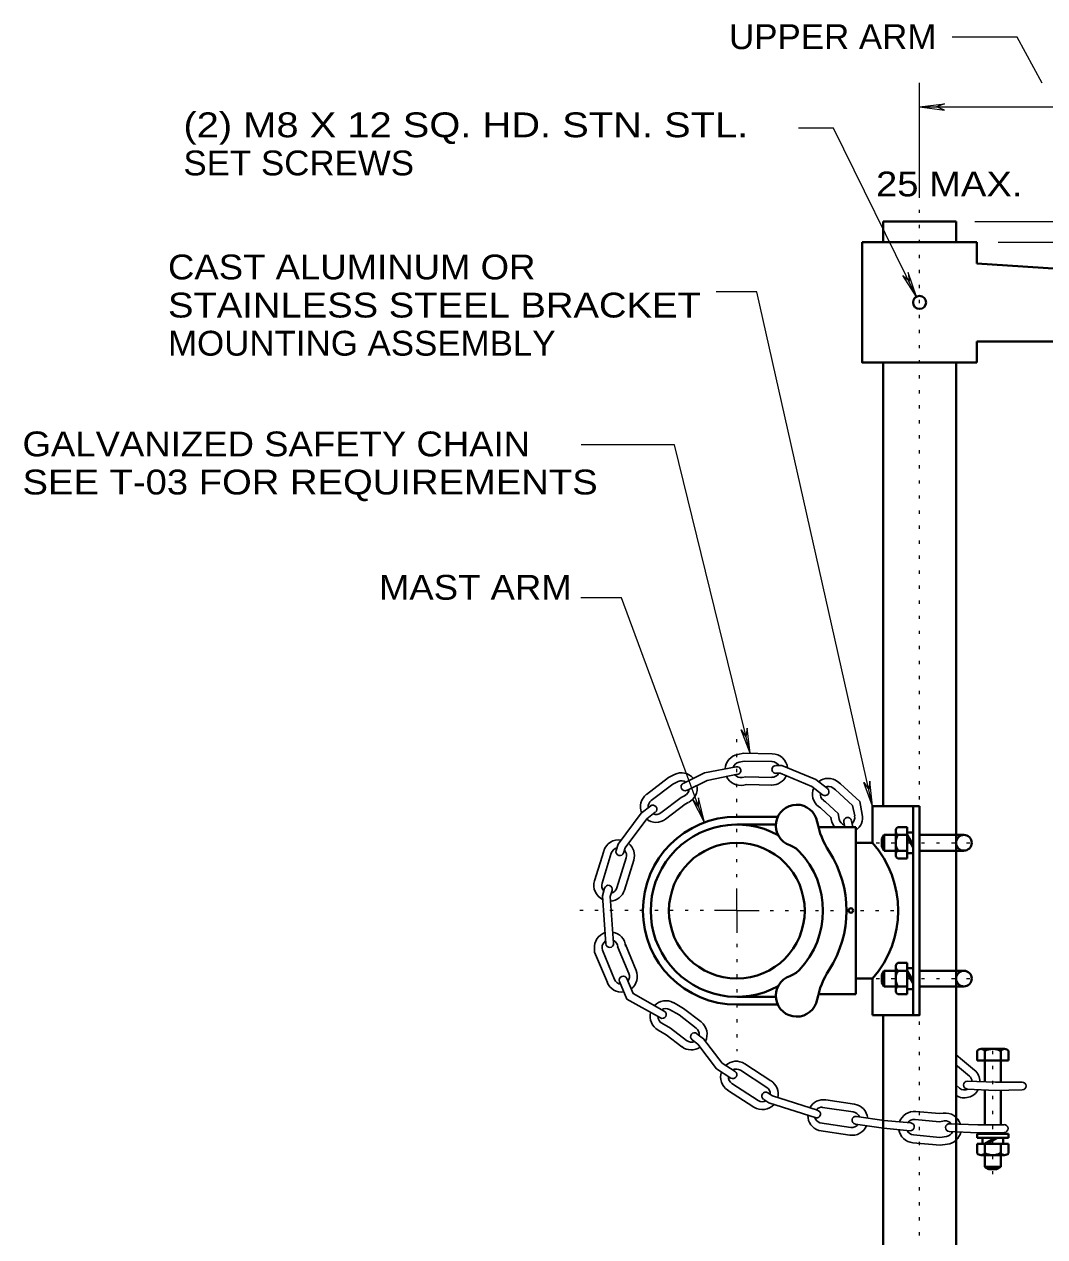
# Model space of a CAD drawing. Extents: x 312583 to 312854, y 144419 to 144597.
# Drawn here: x 312713.71 to 312744.93, y 144479.26 to 144516.36 of the extents above; entities that cross this region are included whole.
import ezdxf

# ---------------------------------------------------------------- set-up
doc = ezdxf.new("R2010")
doc.units = 0
doc.header["$LTSCALE"] = 0.3
doc.linetypes.add('DOTTED', pattern=[1.5, 0.3, -1.2])
doc.layers.add('1', color=7, linetype='Continuous', lineweight=40)
doc.layers.add('2', color=7, linetype='Continuous', lineweight=40)

msp = doc.modelspace()

# ---------------------------------------------------------------- linework, layer by layer
at = {"layer": '1', "linetype": 'DOTTED', "lineweight": 13}
for p, q in [((312741.0994, 144459.9829), (312741.0994, 144511.0659)), ((312739.7731, 144491.3165), (312742.9854, 144491.3165)), ((312739.7731, 144487.1612), (312742.8858, 144487.1612)), ((312743.3381, 144481.1735), (312743.3381, 144485.1832))]:
    msp.add_line(p, q, dxfattribs=at)
at = {"layer": '1'}
for p, q in [((312739.9801, 144509.6859), (312739.9801, 144510.3222)), ((312739.9801, 144510.3222), (312742.2188, 144510.3222)), ((312742.2188, 144509.6859), (312742.2188, 144510.3222)), ((312739.3438, 144509.6859), (312742.8551, 144509.6859)), ((312742.8551, 144509.6859), (312742.8551, 144509.0419)), ((312742.8551, 144509.0419), (312751.8864, 144508.4209)), ((312742.8551, 144506.6499), (312749.7244, 144506.6499)), ((312742.8551, 144506.6499), (312742.8551, 144506.0059)), ((312739.9801, 144492.4359), (312739.9801, 144506.0059)), ((312742.2188, 144466.0779), (312742.2188, 144506.0059)), ((312735.5104, 144492.1139), (312736.7601, 144492.1139)), ((312735.5104, 144491.8762), (312736.6988, 144491.8762)), ((312739.1521, 144491.7919), (312738.0021, 144491.7919)), ((312739.1521, 144491.7919), (312739.1521, 144486.6859)), ((312739.9418, 144491.4315), (312740.0108, 144491.5542)), ((312740.0108, 144491.5542), (312740.0108, 144491.0712)), ((312740.0108, 144491.5542), (312740.3711, 144491.5542)), ((312740.3711, 144491.6769), (312740.3711, 144490.9485)), ((312740.4324, 144491.7919), (312740.7238, 144491.7919)), ((312740.4324, 144491.5542), (312740.7238, 144491.5542)), ((312740.7238, 144491.7919), (312740.7238, 144490.8335)), ((312740.7238, 144491.6309), (312740.9078, 144491.6309)), ((312740.7238, 144491.5542), (312740.9078, 144491.2399)), ((312740.7238, 144491.4929), (312740.9078, 144491.1709)), ((312740.9078, 144491.6309), (312740.9078, 144490.9945)), ((312741.0994, 144491.5542), (312742.4564, 144491.5542)), ((312739.6581, 144491.3165), (312739.1521, 144491.3165)), ((312739.9418, 144491.4315), (312739.9418, 144491.2015)), ((312739.9418, 144491.2015), (312740.0108, 144491.0712)), ((312740.0108, 144491.0712), (312740.3711, 144491.0712)), ((312740.4324, 144491.0712), (312740.7238, 144491.0712)), ((312740.4324, 144490.8335), (312740.7238, 144490.8335)), ((312740.7238, 144490.9945), (312740.9078, 144490.9945)), ((312741.0994, 144491.0712), (312742.4564, 144491.0712)), ((312739.9418, 144487.2762), (312740.0108, 144487.3989)), ((312740.0108, 144487.3989), (312740.0108, 144486.9235)), ((312740.0108, 144487.3989), (312740.3711, 144487.3989)), ((312740.3711, 144487.5215), (312740.3711, 144486.8009)), ((312740.4324, 144487.6442), (312740.7238, 144487.6442)), ((312740.4324, 144487.3989), (312740.7238, 144487.3989)), ((312740.7238, 144487.6442), (312740.7238, 144486.6859)), ((312740.7238, 144487.4832), (312740.9078, 144487.4832)), ((312740.7238, 144487.3989), (312740.9078, 144487.0845)), ((312740.9078, 144487.4832), (312740.9078, 144486.8392)), ((312741.0994, 144487.3989), (312742.4564, 144487.3989)), ((312739.6581, 144487.1612), (312739.1521, 144487.1612)), ((312739.6581, 144486.0419), (312739.6581, 144487.1612)), ((312739.9418, 144487.2762), (312739.9418, 144487.0462)), ((312739.9418, 144487.0462), (312740.0108, 144486.9235)), ((312740.7238, 144487.3375), (312740.9078, 144487.0232)), ((312739.1521, 144486.6859), (312738.0021, 144486.6859)), ((312740.0108, 144486.9235), (312740.3711, 144486.9235)), ((312740.4324, 144486.9235), (312740.7238, 144486.9235)), ((312740.4324, 144486.6859), (312740.7238, 144486.6859)), ((312740.7238, 144486.8392), (312740.9078, 144486.8392)), ((312741.0994, 144486.9235), (312742.4564, 144486.9235)), ((312735.5104, 144486.6015), (312736.6988, 144486.6015)), ((312735.5104, 144486.3639), (312736.7601, 144486.3639)), ((312739.9801, 144476.1442), (312739.9801, 144486.0419)), ((312742.8628, 144484.9532), (312742.8628, 144484.6542)), ((312742.9778, 144485.0069), (312743.7061, 144485.0069)), ((312743.1004, 144483.9949), (312743.1004, 144484.9532)), ((312743.5834, 144483.9872), (312743.5834, 144484.9532)), ((312743.8211, 144484.9532), (312743.8211, 144484.6542)), ((312742.8628, 144484.6542), (312743.8211, 144484.6542)), ((312743.1004, 144482.6839), (312743.1004, 144483.7572)), ((312743.5834, 144482.6915), (312743.5834, 144483.7495)), ((312742.8628, 144482.4079), (312743.8211, 144482.4079)), ((312742.8628, 144482.2929), (312742.8628, 144482.4079)), ((312742.8628, 144482.2929), (312743.8211, 144482.2929)), ((312743.0238, 144482.1089), (312743.0238, 144482.2929)), ((312743.1004, 144482.4079), (312743.1004, 144482.4462)), ((312743.1004, 144482.1089), (312743.4148, 144482.2929)), ((312743.1618, 144482.1089), (312743.4838, 144482.2929)), ((312743.5834, 144482.4079), (312743.5834, 144482.4539)), ((312743.6601, 144482.1089), (312743.6601, 144482.2929)), ((312743.8211, 144482.2929), (312743.8211, 144482.4079)), ((312742.8628, 144482.1089), (312743.8211, 144482.1089)), ((312742.8628, 144481.8175), (312742.8628, 144482.1089)), ((312743.1004, 144481.8175), (312743.1004, 144482.1089)), ((312743.5834, 144481.8175), (312743.5834, 144482.1089)), ((312743.8211, 144481.8175), (312743.8211, 144482.1089)), ((312742.9778, 144481.7562), (312743.7061, 144481.7562)), ((312743.1004, 144481.4035), (312743.1004, 144481.7562)), ((312743.5834, 144481.4035), (312743.5834, 144481.7562)), ((312743.1004, 144481.4035), (312743.5834, 144481.4035)), ((312743.2231, 144481.3269), (312743.1004, 144481.4035)), ((312743.2231, 144481.3269), (312743.4531, 144481.3269)), ((312743.4531, 144481.3269), (312743.5834, 144481.4035))]:
    msp.add_line(p, q, dxfattribs=at)
at = {"layer": '1', "lineweight": 25}
for p, q in [((312742.4104, 144484.6695), (312742.2188, 144484.8305)), ((312742.2571, 144484.4855), (312742.2188, 144484.5162)), ((312742.2571, 144484.4855), (312742.6251, 144484.1789)), ((312742.4104, 144484.6695), (312742.7784, 144484.3552)), ((312742.3184, 144483.8109), (312742.2188, 144483.8952))]:
    msp.add_line(p, q, dxfattribs=at)
at = {"layer": '1'}
for points in [[(312739.3438, 144509.6859), (312739.3438, 144506.0059), (312742.8551, 144506.0059)], [(312741.0994, 144492.4359), (312741.0994, 144486.0419), (312739.6581, 144486.0419)], [(312741.0994, 144492.4359), (312739.6581, 144492.4359), (312739.6581, 144491.3165)], [(312741.0994, 144492.4359), (312740.9078, 144492.4359), (312740.9078, 144486.0419)]]:
    msp.add_lwpolyline(points, dxfattribs=at)
for centre, radius in [((312741.0982, 144507.8459), 0.1996), ((312742.4558, 144491.3146), 0.2396), ((312735.5079, 144489.2382), 2.0764), ((312738.9968, 144489.2446), 0.0679), ((312742.4558, 144487.1618), 0.2396)]:
    msp.add_circle(centre, radius, dxfattribs=at)
for centre, radius, start, end in [((312735.5079, 144489.2382), 2.875, 90, 270), ((312735.5079, 144489.2382), 2.6354, 61.35961, 298.6449), ((312740.4794, 144492.4334), 2.5556, 190.67393, 212.72852), ((312740.5225, 144491.674), 0.1515, 127.72221, 232.27779), ((312740.8887, 144491.3146), 0.5176, 152.42977, 207.57023), ((312735.5079, 144489.2382), 2.6354, 316.47333, 43.52667), ((312735.5079, 144489.2382), 3.3542, 327.27148, 32.72852), ((312740.5225, 144490.9552), 0.1515, 127.72221, 232.27779), ((312740.4794, 144486.0431), 2.5556, 147.27148, 169.32607), ((312740.5225, 144487.5212), 0.1515, 127.72221, 232.27779), ((312740.8887, 144487.1618), 0.5176, 152.42977, 207.57023), ((312740.5225, 144486.8025), 0.1515, 127.72221, 232.27779), ((312742.9806, 144484.858), 0.1515, 37.72221, 142.27779), ((312743.34, 144484.4918), 0.5176, 62.42977, 117.57023), ((312743.6994, 144484.858), 0.1515, 37.72221, 142.27779), ((312742.9806, 144481.9115), 0.1515, 217.72221, 322.27779), ((312743.34, 144482.2777), 0.5176, 242.42977, 297.57023), ((312743.6994, 144481.9115), 0.1515, 217.72221, 322.27779)]:
    msp.add_arc(centre, radius, start, end, dxfattribs=at)
at = {"layer": '2', "lineweight": 13}
for p, q in [((312744.0818, 144515.9649), (312742.0961, 144515.9649)), ((312744.8484, 144514.5542), (312744.0818, 144515.9649)), ((312741.0994, 144511.0659), (312741.0994, 144514.5619)), ((312741.0994, 144513.8259), (312741.8661, 144513.9179)), ((312741.0994, 144513.8259), (312753.2204, 144513.8259)), ((312741.0994, 144513.8259), (312741.8661, 144513.7262)), ((312741.8661, 144513.9179), (312741.6208, 144513.8259)), ((312741.8661, 144513.7262), (312741.6208, 144513.8259)), ((312738.4621, 144513.1742), (312737.3964, 144513.1742)), ((312741.0074, 144508.0222), (312738.4621, 144513.1742)), ((312742.7861, 144510.3222), (312746.5044, 144510.3222)), ((312743.4991, 144509.6859), (312746.9874, 144509.6859)), ((312740.5858, 144508.6739), (312740.7774, 144508.4975)), ((312741.0074, 144508.0222), (312740.5858, 144508.6739)), ((312740.7544, 144508.7582), (312740.7774, 144508.4975)), ((312741.0074, 144508.0222), (312740.7544, 144508.7582)), ((312736.1238, 144508.1679), (312734.8741, 144508.1679)), ((312739.6581, 144492.4359), (312736.1238, 144508.1679)), ((312733.6014, 144503.4912), (312730.7494, 144503.4912)), ((312735.9168, 144494.0535), (312733.6014, 144503.4912)), ((312731.9838, 144498.8069), (312730.7341, 144498.8069)), ((312734.5138, 144491.9375), (312731.9838, 144498.8069)), ((312735.8248, 144494.8202), (312735.7864, 144494.5595)), ((312735.9168, 144494.0535), (312735.8248, 144494.8202)), ((312735.6408, 144494.7742), (312735.7864, 144494.5595)), ((312735.9168, 144494.0535), (312735.6408, 144494.7742)), ((312739.3974, 144493.1642), (312739.5431, 144492.9419)), ((312739.6581, 144492.4359), (312739.3974, 144493.1642)), ((312739.5814, 144493.2025), (312739.5431, 144492.9419)), ((312739.6581, 144492.4359), (312739.5814, 144493.2025)), ((312734.1611, 144492.6275), (312734.3298, 144492.4282)), ((312734.5138, 144491.9375), (312734.1611, 144492.6275)), ((312734.3374, 144492.6889), (312734.3298, 144492.4282)), ((312734.5138, 144491.9375), (312734.3374, 144492.6889)), ((312735.5104, 144489.2389), (312735.5104, 144489.9212)), ((312735.5104, 144489.2389), (312734.8281, 144489.2389)), ((312735.5104, 144489.2389), (312736.1928, 144489.2389)), ((312735.5104, 144489.2389), (312735.5104, 144488.5565))]:
    msp.add_line(p, q, dxfattribs=at)
at = {"layer": '2', "linetype": 'DOTTED', "lineweight": 13}
for p, q in [((312735.5104, 144490.2585), (312735.5104, 144494.4829)), ((312734.4831, 144489.2389), (312730.5501, 144489.2389)), ((312736.5301, 144489.2389), (312740.4401, 144489.2389)), ((312735.5104, 144488.2192), (312735.5104, 144484.9455))]:
    msp.add_line(p, q, dxfattribs=at)
at = {"layer": '2', "lineweight": 25}
for p, q in [((312738.7841, 144491.9452), (312738.8148, 144491.7919)), ((312739.0141, 144491.9912), (312739.0524, 144491.7919)), ((312731.1558, 144490.1512), (312731.4394, 144491.0635)), ((312731.3858, 144490.0822), (312731.6618, 144490.9945)), ((312731.8381, 144489.9365), (312732.1218, 144490.8565)), ((312732.0681, 144489.8675), (312732.3518, 144490.7875)), ((312736.5531, 144484.0332), (312735.7481, 144484.5545)), ((312736.4228, 144483.8339), (312735.6178, 144484.3552)), ((312736.0318, 144483.2282), (312735.2268, 144483.7495)), ((312736.1621, 144483.4275), (312735.3571, 144483.9489)), ((312739.1061, 144483.3202), (312738.2321, 144483.4505)), ((312739.0678, 144483.0825), (312738.1248, 144483.2205)), ((312738.9988, 144482.6072), (312738.0481, 144482.7452)), ((312738.9681, 144482.3695), (312738.0174, 144482.5152))]:
    msp.add_line(p, q, dxfattribs=at)
for points in [[(312735.5334, 144494.0152), (312735.7174, 144494.0535), (312736.5914, 144494.0382)], [(312735.5794, 144493.7852), (312735.7328, 144493.8159), (312736.5838, 144493.8005)], [(312732.7428, 144492.7962), (312733.4174, 144493.3175), (312733.6014, 144493.4019)], [(312733.8698, 144493.1335), (312734.5214, 144493.4555), (312735.4874, 144493.6395)], [(312733.9771, 144492.9189), (312734.5981, 144493.2255), (312735.5334, 144493.4095)], [(312735.6714, 144493.3175), (312735.7788, 144493.3329), (312736.5761, 144493.3175)], [(312736.6988, 144493.4402), (312736.8368, 144493.4402), (312737.8028, 144493.0415), (312738.1324, 144492.7809)], [(312736.7064, 144493.6779), (312736.8828, 144493.6779), (312737.9254, 144493.2485), (312738.2781, 144492.9725)], [(312732.8884, 144492.6122), (312733.5478, 144493.1105), (312733.7088, 144493.1872)], [(312735.7174, 144493.0799), (312735.8018, 144493.0952), (312736.5761, 144493.0799)], [(312738.4468, 144492.9955), (312738.5311, 144492.9342), (312739.0448, 144492.4589), (312739.1138, 144492.1369)], [(312738.5924, 144493.1872), (312738.6844, 144493.1182), (312739.2671, 144492.5815), (312739.3438, 144492.1829)], [(312733.1798, 144492.2289), (312733.8008, 144492.7042), (312733.9234, 144492.7579)], [(312738.1554, 144492.6122), (312738.2168, 144492.5662), (312738.6078, 144492.2135), (312738.6384, 144492.0372)], [(312731.8151, 144491.0789), (312731.8764, 144491.2705), (312732.5818, 144492.2212), (312732.8731, 144492.4435)], [(312732.0451, 144491.0022), (312732.0911, 144491.1632), (312732.7581, 144492.0525), (312733.0111, 144492.2519)], [(312733.3254, 144492.0372), (312733.9234, 144492.4972), (312734.0231, 144492.5432)], [(312738.0098, 144492.4205), (312738.0634, 144492.3822), (312738.3854, 144492.0909), (312738.4084, 144491.9912)], [(312731.5008, 144488.2269), (312731.3934, 144489.6912), (312731.4624, 144489.9289)], [(312731.7384, 144488.2422), (312731.6311, 144489.6682), (312731.6924, 144489.8599)], [(312732.2061, 144487.3145), (312731.8611, 144488.1425), (312731.8688, 144488.1349)], [(312732.4284, 144487.4065), (312732.0988, 144488.2039), (312732.1064, 144488.1502)], [(312731.5468, 144487.0462), (312731.1558, 144487.9739), (312731.1481, 144488.0735)], [(312731.7614, 144487.1305), (312731.3934, 144488.0352), (312731.3858, 144488.0965)], [(312733.1721, 144485.9575), (312732.1448, 144486.5325), (312731.9224, 144487.0692)], [(312733.2871, 144486.1645), (312732.3364, 144486.7012), (312732.1448, 144487.1612)], [(312734.4141, 144485.8349), (312733.8774, 144486.2489), (312733.5708, 144486.4252)], [(312734.2684, 144485.6432), (312733.7471, 144486.0495), (312733.4481, 144486.2105)], [(312733.8238, 144485.0759), (312733.3484, 144485.4439), (312733.1031, 144485.5819)], [(312733.9694, 144485.2675), (312733.4788, 144485.6432), (312733.2181, 144485.7965)], [(312735.3264, 144484.1175), (312734.8894, 144484.4012), (312734.3144, 144485.1525), (312734.1381, 144485.2905)], [(312735.4568, 144484.3169), (312735.0581, 144484.5775), (312734.4908, 144485.3212), (312734.2838, 144485.4745)], [(312744.2351, 144483.7572), (312743.4224, 144483.7419), (312742.5561, 144483.7802)], [(312744.2351, 144483.9949), (312743.4224, 144483.9872), (312742.5638, 144484.0179)], [(312737.9331, 144482.8985), (312736.4918, 144483.3585), (312736.3308, 144483.4659)], [(312737.9714, 144483.1362), (312736.5991, 144483.5732), (312736.4611, 144483.6652)], [(312740.8311, 144482.7452), (312740.0184, 144482.8219), (312739.1674, 144482.9445)], [(312741.8201, 144483.0442), (312741.7051, 144483.0289), (312740.9844, 144483.0902)], [(312740.8081, 144482.5075), (312739.9954, 144482.5842), (312739.1368, 144482.7069)], [(312741.8584, 144482.8065), (312741.7128, 144482.7835), (312740.9614, 144482.8525)], [(312743.6831, 144482.6915), (312742.8781, 144482.6839), (312742.0194, 144482.7222)], [(312741.9198, 144482.3312), (312741.7204, 144482.3005), (312740.9154, 144482.3772)], [(312743.6908, 144482.4539), (312742.8704, 144482.4462), (312742.0041, 144482.4845)], [(312741.9581, 144482.0935), (312741.7281, 144482.0629), (312740.8924, 144482.1395)]]:
    msp.add_lwpolyline(points, dxfattribs=at)
for centre, radius, start, end in [((312735.6264, 144493.5491), 0.4792, 101.14556, 176.62859), ((312735.6264, 144493.5491), 0.2396, 101.14556, 161.05731), ((312736.5818, 144493.5602), 0.2396, 29.0581, 88.96985), ((312736.5818, 144493.5602), 0.4792, 5.05092, 89.00409), ((312733.8147, 144492.9752), 0.4792, 40.56675, 116.04979), ((312735.6264, 144493.5491), 0.4792, 205.50476, 281.14556), ((312735.6264, 144493.5491), 0.2396, 220.88127, 281.14556), ((312735.5086, 144493.5259), 0.1195, 281.14556, 101.14556), ((312736.5818, 144493.5602), 0.4792, 268.93347, 335.48236), ((312736.5818, 144493.5602), 0.2396, 268.96985, 329.23414), ((312736.7019, 144493.558), 0.1195, 88.96985, 268.96985), ((312733.8147, 144492.9752), 0.2396, 56.13804, 116.04979), ((312733.9226, 144493.028), 0.1195, 116.04979, 296.04979), ((312733.8147, 144492.9752), 0.2396, 296.04979, 356.31408), ((312733.8147, 144492.9752), 0.4792, 296.04979, 11.69059), ((312738.3012, 144492.8044), 0.4792, 156.84249, 232.4833), ((312738.3012, 144492.8044), 0.4792, 52.4833, 127.96633), ((312738.2059, 144492.8776), 0.1195, 232.4833, 52.4833), ((312738.3012, 144492.8044), 0.2396, 52.4833, 112.39505), ((312733.0374, 144492.4195), 0.4792, 127.41484, 202.89787), ((312733.0374, 144492.4195), 0.2396, 127.41484, 187.32659), ((312738.3012, 144492.8044), 0.2396, 172.21901, 232.4833), ((312732.942, 144492.3466), 0.1195, 307.41484, 127.41484), ((312733.0374, 144492.4195), 0.2396, 247.15055, 307.41484), ((312733.0374, 144492.4195), 0.4792, 231.77403, 307.41484), ((312738.8469, 144492.0893), 0.452, 191.2806, 220.81754), ((312738.875, 144492.0867), 0.2396, 191.30993, 251.57422), ((312738.8985, 144491.9689), 0.1195, 11.30993, 191.30993), ((312738.875, 144492.0867), 0.2396, 311.39818, 11.30993), ((312738.875, 144492.0867), 0.4792, 304.95841, 11.3376), ((312731.8941, 144490.926), 0.4792, 80.81337, 162.91712), ((312731.8941, 144490.926), 0.2396, 102.98049, 162.89224), ((312731.8941, 144490.926), 0.4792, 342.87181, 51.25081), ((312731.9294, 144491.0408), 0.1195, 162.89224, 342.89224), ((312731.8941, 144490.926), 0.2396, 342.89224, 43.15653), ((312731.6122, 144490.0101), 0.4792, 162.86539, 243.45169), ((312731.6122, 144490.0101), 0.2396, 162.89224, 222.80399), ((312731.5768, 144489.8953), 0.1195, 342.89224, 162.89224), ((312731.6122, 144490.0101), 0.4792, 273.4661, 342.92353), ((312731.6122, 144490.0101), 0.2396, 282.62795, 342.89224), ((312731.6267, 144488.1134), 0.4792, 108.73644, 184.21947), ((312731.6267, 144488.1134), 0.4792, 4.21947, 79.86028), ((312731.6267, 144488.1134), 0.2396, 124.30772, 184.21947), ((312731.6179, 144488.2332), 0.1195, 184.21947, 4.21947), ((312731.6267, 144488.1134), 0.2396, 4.21947, 64.48376), ((312731.9852, 144487.2264), 0.4792, 306.8379, 22.4787), ((312731.9852, 144487.2264), 0.4792, 202.4787, 277.96174), ((312731.9852, 144487.2264), 0.2396, 202.4787, 262.39045), ((312732.0312, 144487.1154), 0.1195, 22.4787, 202.4787), ((312731.9852, 144487.2264), 0.2396, 322.21441, 22.4787), ((312733.3335, 144486.0043), 0.4792, 60.8687, 136.50951), ((312733.3335, 144486.0043), 0.4792, 165.38567, 240.8687), ((312733.3335, 144486.0043), 0.2396, 180.95695, 240.8687), ((312733.2285, 144486.0628), 0.1195, 240.8687, 60.8687), ((312733.3335, 144486.0043), 0.2396, 60.8687, 121.13299), ((312734.1179, 144485.4577), 0.2396, 351.96075, 52.22504), ((312734.1179, 144485.4577), 0.4792, 333.52346, 52.19135), ((312734.1179, 144485.4577), 0.2396, 232.22504, 292.13679), ((312734.2128, 144485.3841), 0.1195, 52.22504, 232.22504), ((312734.1179, 144485.4577), 0.4792, 232.21953, 304.02287), ((312735.4897, 144484.1539), 0.4792, 56.97531, 132.61612), ((312735.4897, 144484.1539), 0.4792, 161.49228, 236.97531), ((312735.4897, 144484.1539), 0.2396, 177.06356, 236.97531), ((312735.389, 144484.2193), 0.1195, 236.97531, 56.97531), ((312735.4897, 144484.1539), 0.2396, 56.97531, 117.2396), ((312742.4704, 144483.9917), 0.2396, 5.54994, 49.95095), ((312742.4704, 144483.9917), 0.4792, 1.52961, 50.01415), ((312736.3939, 144483.5661), 0.1195, 56.97531, 236.97531), ((312736.2932, 144483.6316), 0.2396, 356.71103, 56.97531), ((312736.2932, 144483.6316), 0.4792, 346.95996, 56.95903), ((312742.4704, 144483.9917), 0.4792, 237.96321, 332.10108), ((312742.4704, 144483.9917), 0.2396, 230.00726, 298.35146), ((312742.5607, 144483.9018), 0.1195, 87.54765, 267.54765), ((312744.2363, 144483.8756), 0.1195, 270.75156, 90.75156), ((312736.2932, 144483.6316), 0.4792, 236.93237, 317.63946), ((312736.2932, 144483.6316), 0.2396, 236.97531, 296.88706), ((312738.162, 144482.9771), 0.4792, 81.77748, 151.05142), ((312739.0342, 144482.8449), 0.4792, 5.90685, 81.54765), ((312738.1626, 144482.9676), 0.4792, 178.8753, 252.27606), ((312737.947, 144483.0169), 0.1195, 261.54765, 81.54765), ((312738.1121, 144482.9861), 0.2396, 84.75253, 137.61712), ((312739.153, 144482.8273), 0.1195, 81.54765, 261.54765), ((312739.0342, 144482.8449), 0.2396, 21.28336, 81.54765), ((312740.9362, 144482.6151), 0.4792, 84.75156, 160.39237), ((312741.8893, 144482.5674), 0.4792, 16.88913, 97.99467), ((312738.123, 144482.9791), 0.2396, 196.83176, 252.26184), ((312739.0342, 144482.8449), 0.4792, 261.54765, 337.03069), ((312739.0342, 144482.8449), 0.2396, 261.54765, 321.4594), ((312740.9362, 144482.6151), 0.2396, 84.75156, 145.01585), ((312740.8166, 144482.6261), 0.1195, 264.75156, 84.75156), ((312741.8893, 144482.5674), 0.2396, 39.05887, 98.01063), ((312742.0113, 144482.6017), 0.1195, 87.54765, 267.54765), ((312743.6868, 144482.5754), 0.1195, 270.75156, 90.75156), ((312740.9362, 144482.6151), 0.4792, 189.26853, 264.75156), ((312740.9362, 144482.6151), 0.2396, 204.83981, 264.75156), ((312741.8893, 144482.5674), 0.2396, 277.92562, 337.93102), ((312741.8893, 144482.5674), 0.4792, 277.95213, 347.86178)]:
    msp.add_arc(centre, radius, start, end, dxfattribs=at)
at = {"layer": '2'}
for centre, radius, start, end in [((312737.3402, 144491.8417), 0.6389, 10.67393, 250.96957), ((312736.8975, 144490.5583), 0.7188, 43.52836, 70.96956), ((312737.2899, 144489.2382), 3.1515, 318.78748, 41.21252), ((312736.8975, 144487.9182), 0.7188, 289.03044, 316.47164), ((312737.3402, 144486.6348), 0.6389, 109.03043, 349.32607)]:
    msp.add_arc(centre, radius, start, end, dxfattribs=at)

# ---------------------------------------------------------------- texts
for s, width, p in [('UPPER ARM', 1.05, (312735.2696, 144515.5966)), ('(2) M8 X 12 SQ. HD. STN. STL.', 1.2, (312718.5762, 144512.8995)), ('SET SCREWS', 1.05, (312718.5762, 144511.7332)), ('25 MAX.', 1.15, (312739.7656, 144511.0897)), ('CAST ALUMINUM OR', 1.1, (312718.1037, 144508.5509)), ('STAINLESS STEEL BRACKET', 1.15, (312718.1037, 144507.3846)), ('MOUNTING ASSEMBLY', 1.05, (312718.1037, 144506.2183)), ('GALVANIZED SAFETY CHAIN', 1.1, (312713.6528, 144503.1375)), ('SEE T-03 FOR REQUIREMENTS', 1.15, (312713.6528, 144501.9712)), ('MAST ARM', 1.1, (312724.5563, 144498.7509))]:
    msp.add_text(s, height=0.76, dxfattribs=dict(at, width=width)).set_placement(p)

doc.saveas('drawing.dxf')
